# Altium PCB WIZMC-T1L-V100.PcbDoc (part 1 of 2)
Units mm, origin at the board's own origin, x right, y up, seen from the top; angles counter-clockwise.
Board outline 48.5 x 42.5 mm, 4 copper layers (Top Layer, GND, POWER, Bottom Layer), stack 0.603 mm thick; 133 components, 92 nets, 478 pads, 203 vias.
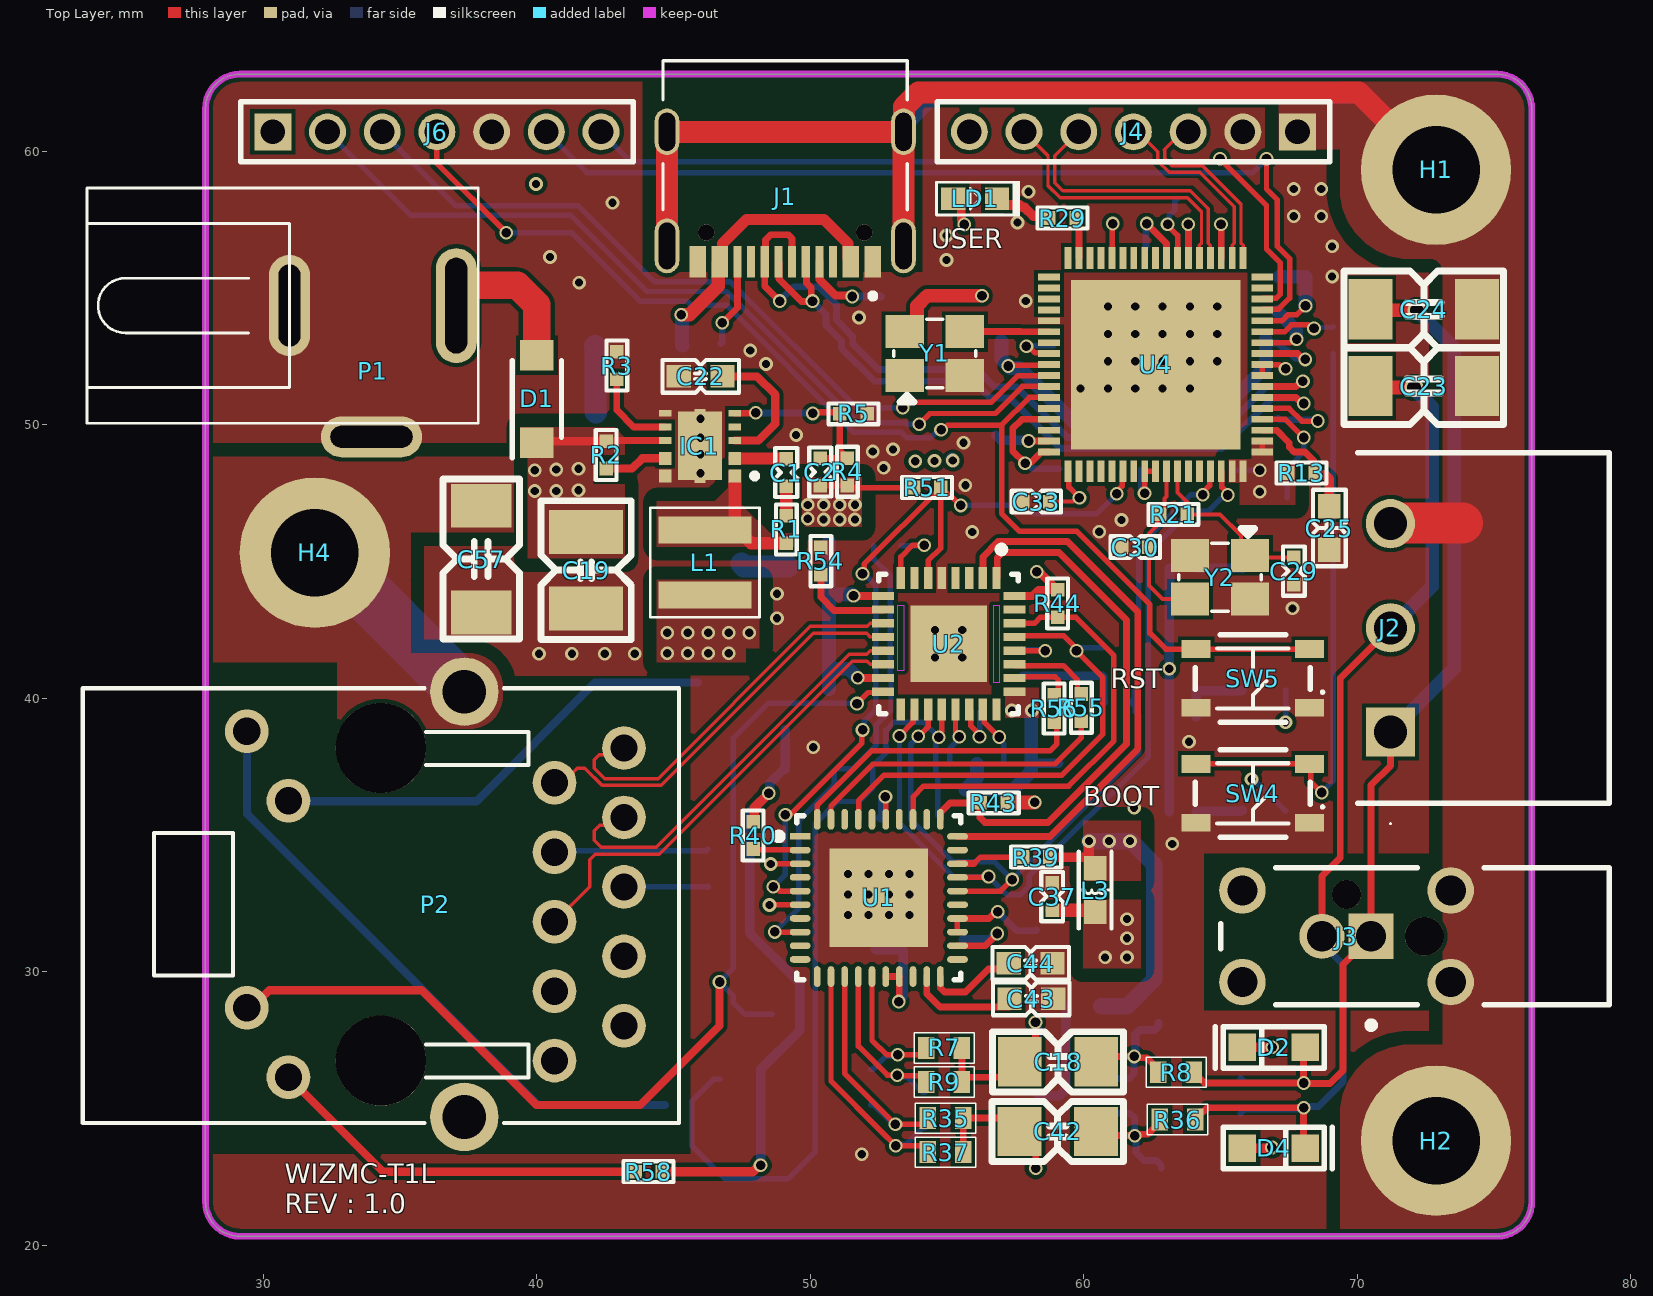
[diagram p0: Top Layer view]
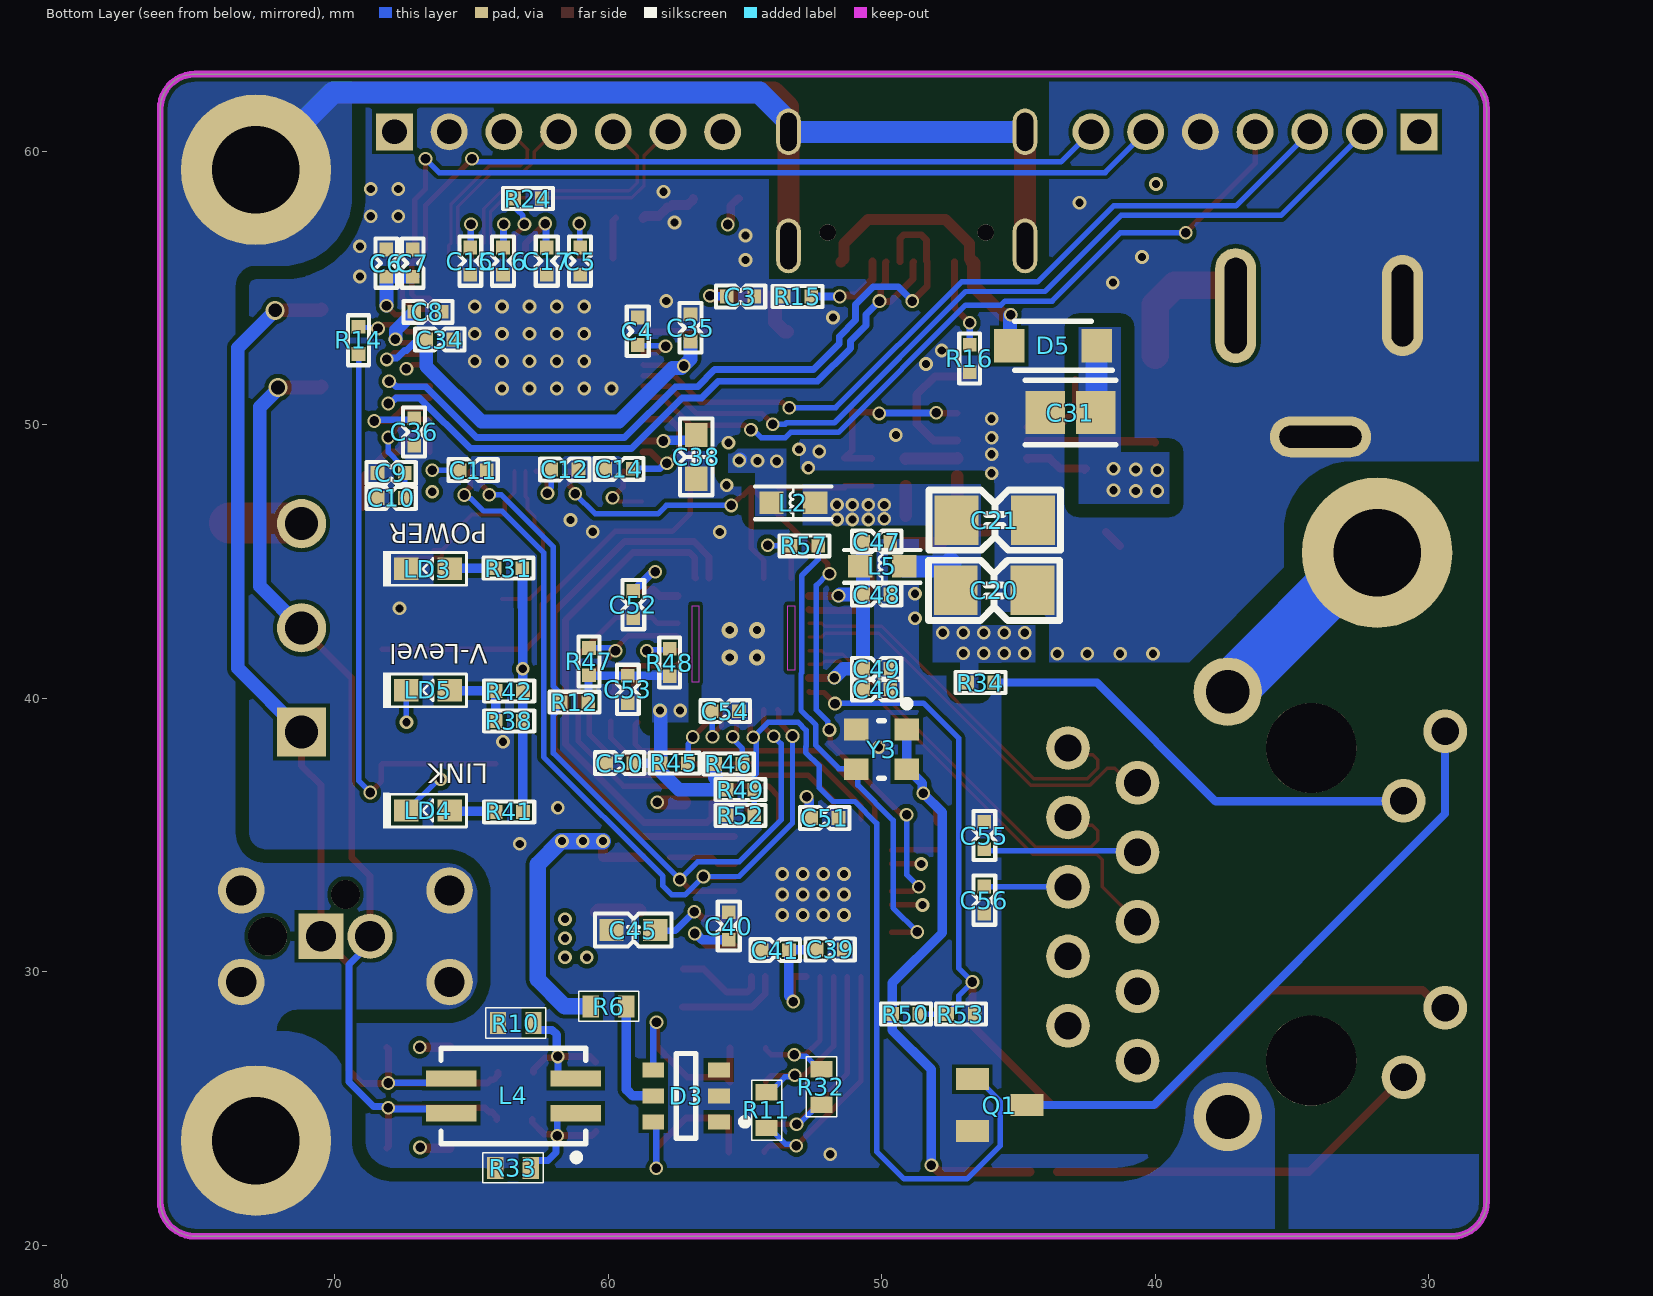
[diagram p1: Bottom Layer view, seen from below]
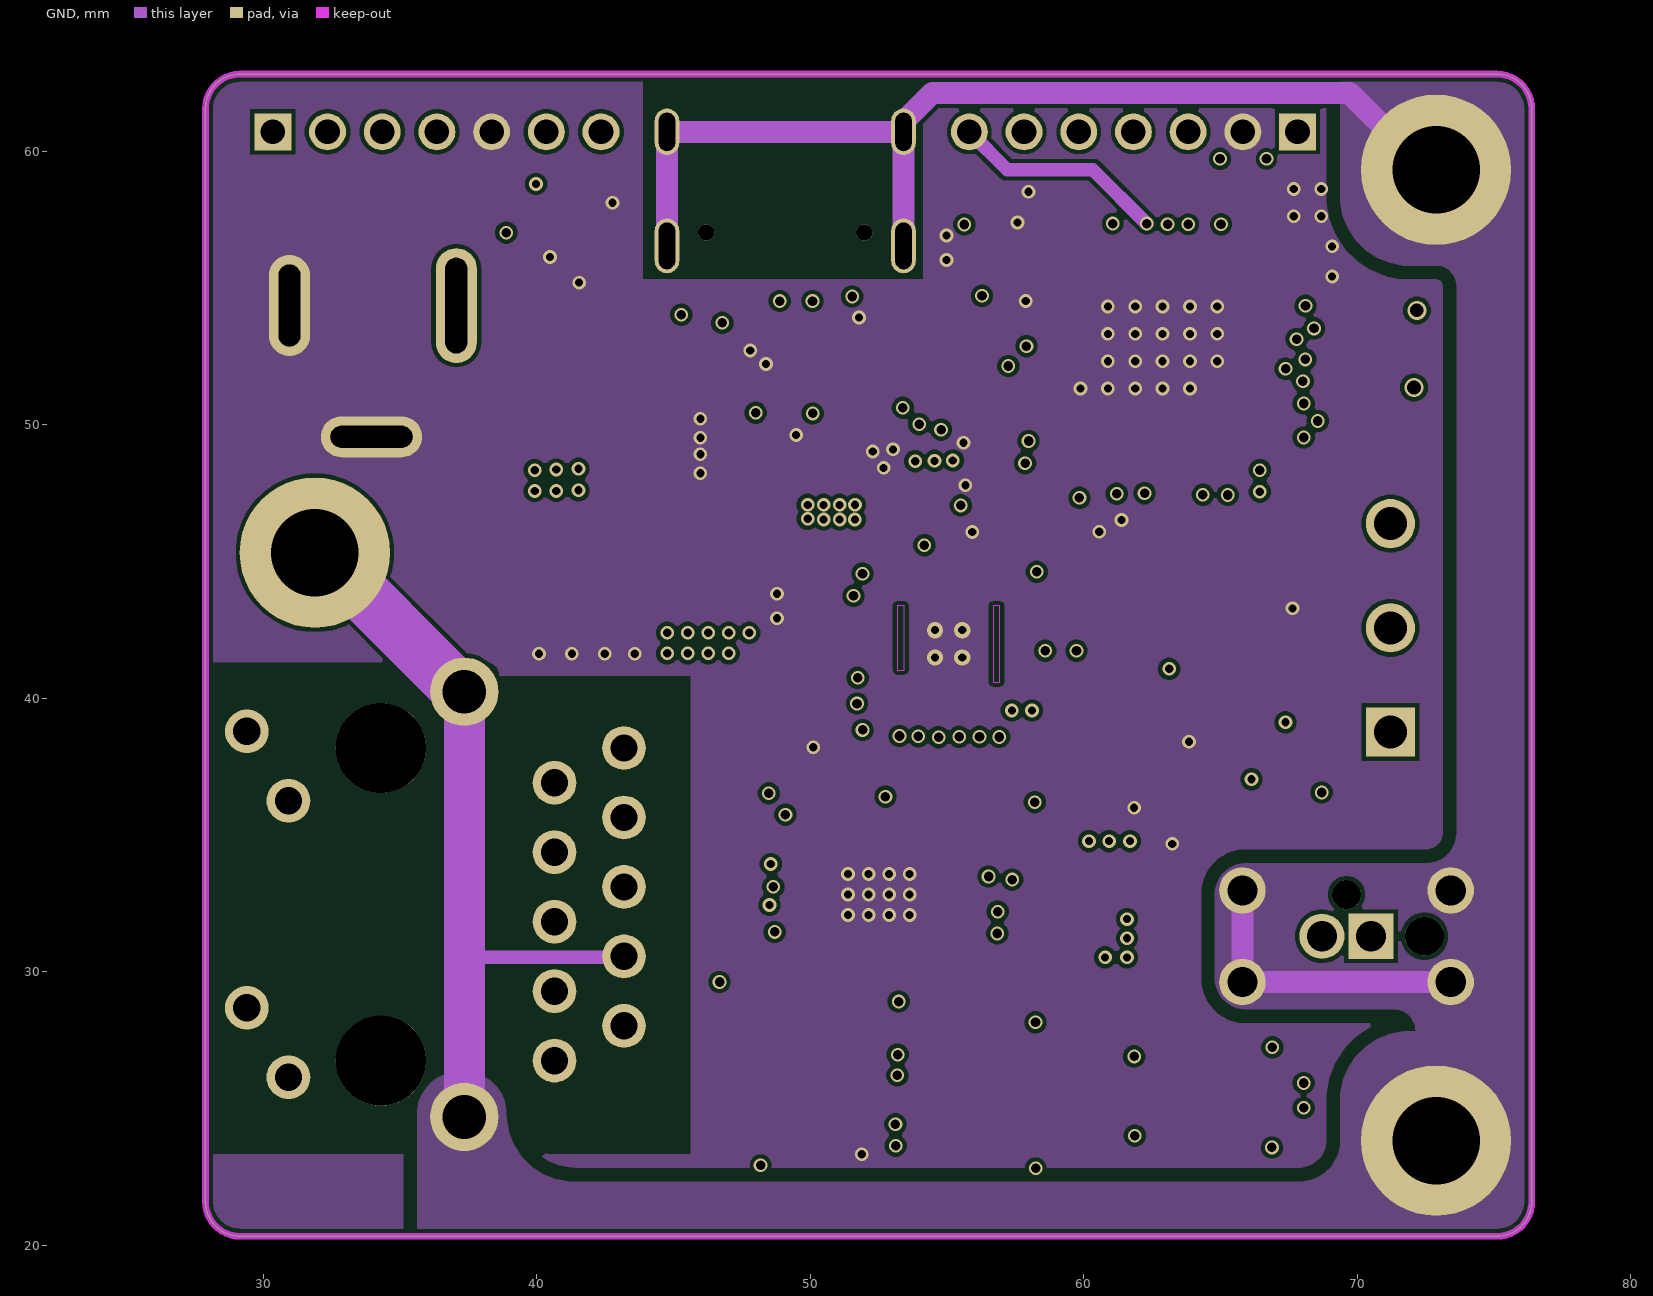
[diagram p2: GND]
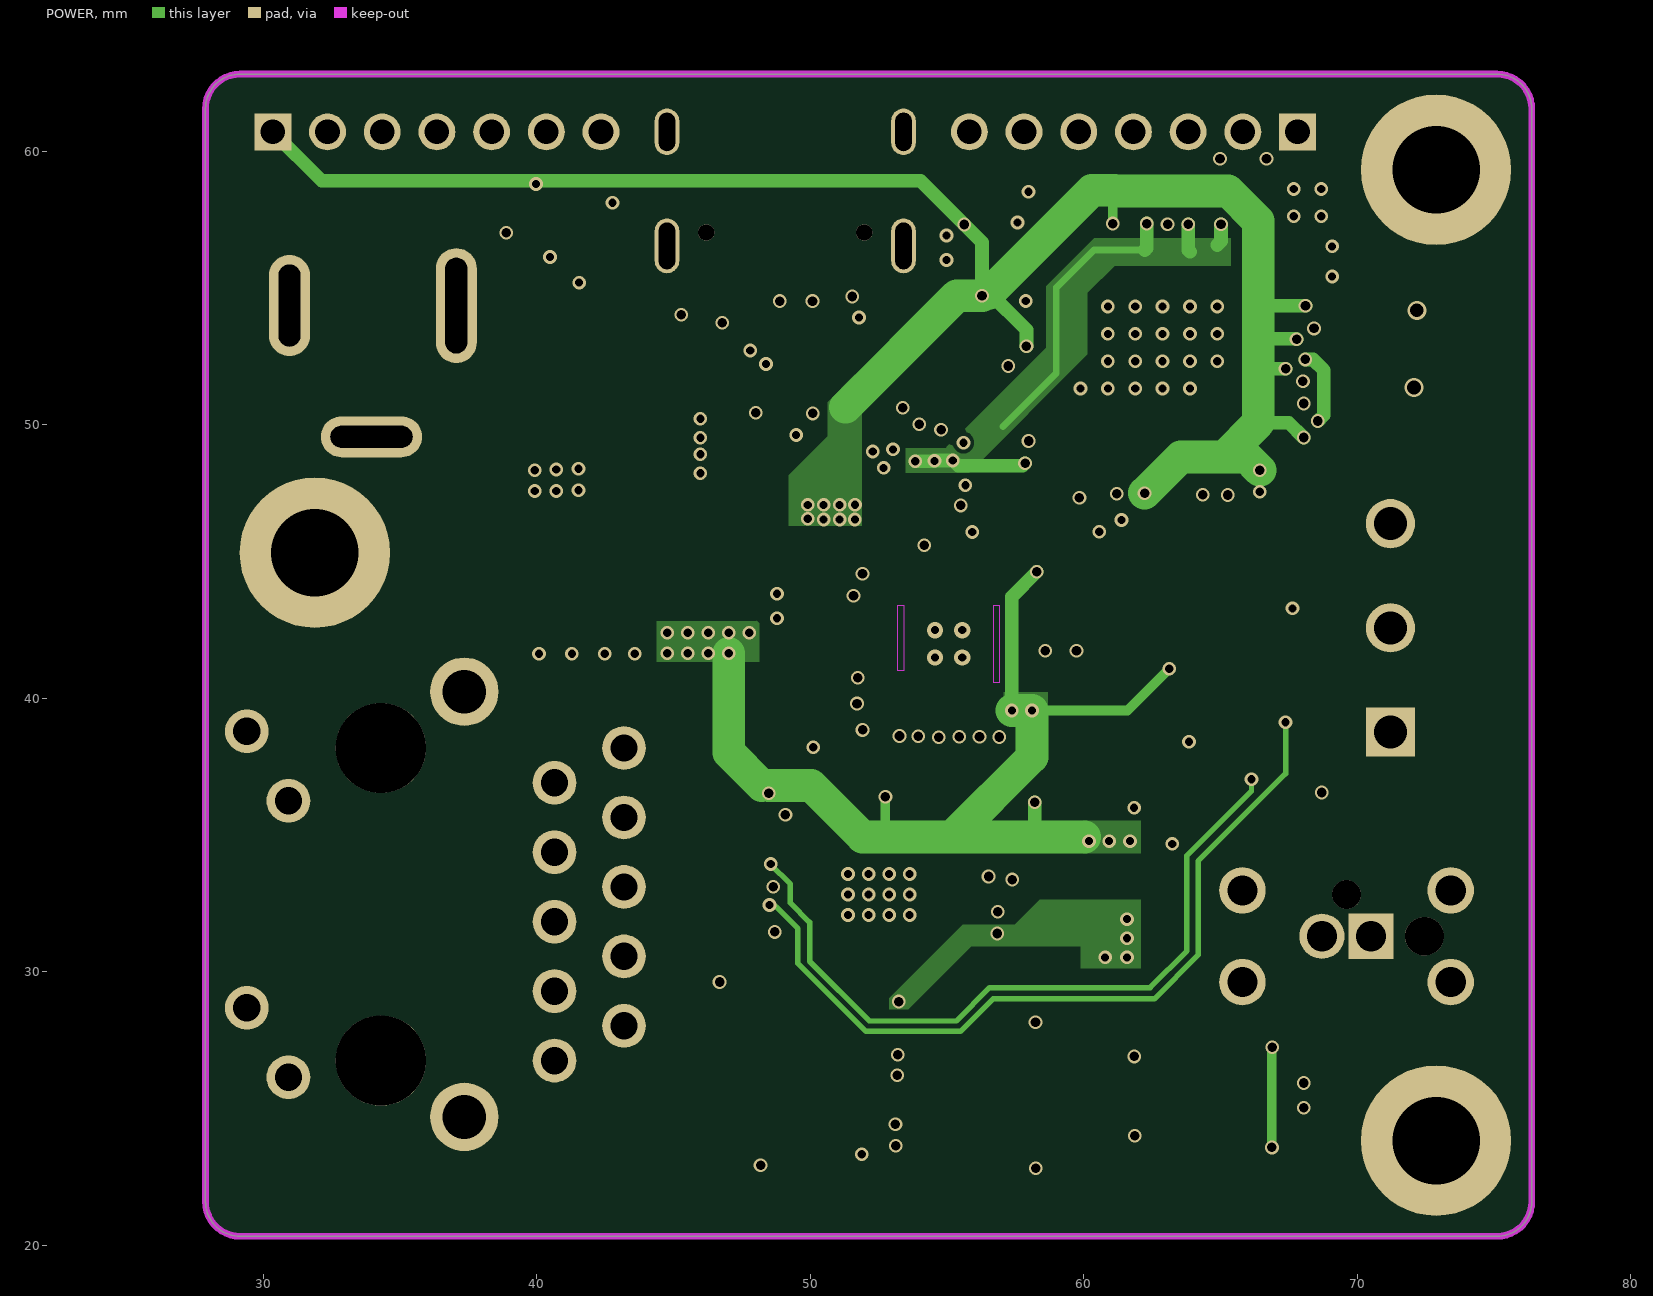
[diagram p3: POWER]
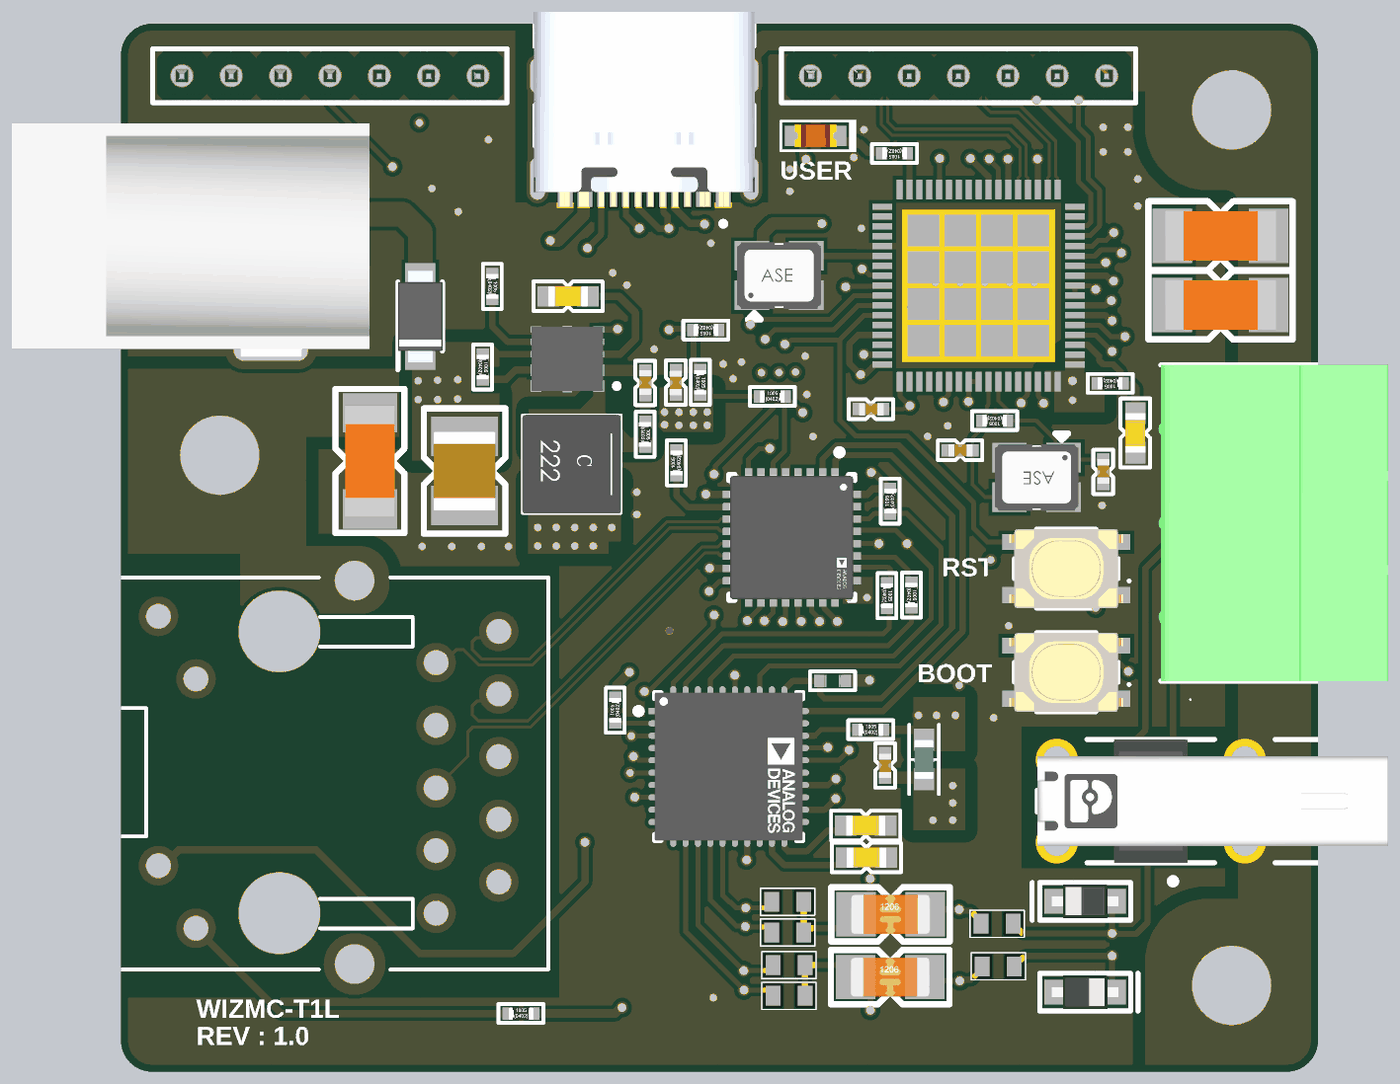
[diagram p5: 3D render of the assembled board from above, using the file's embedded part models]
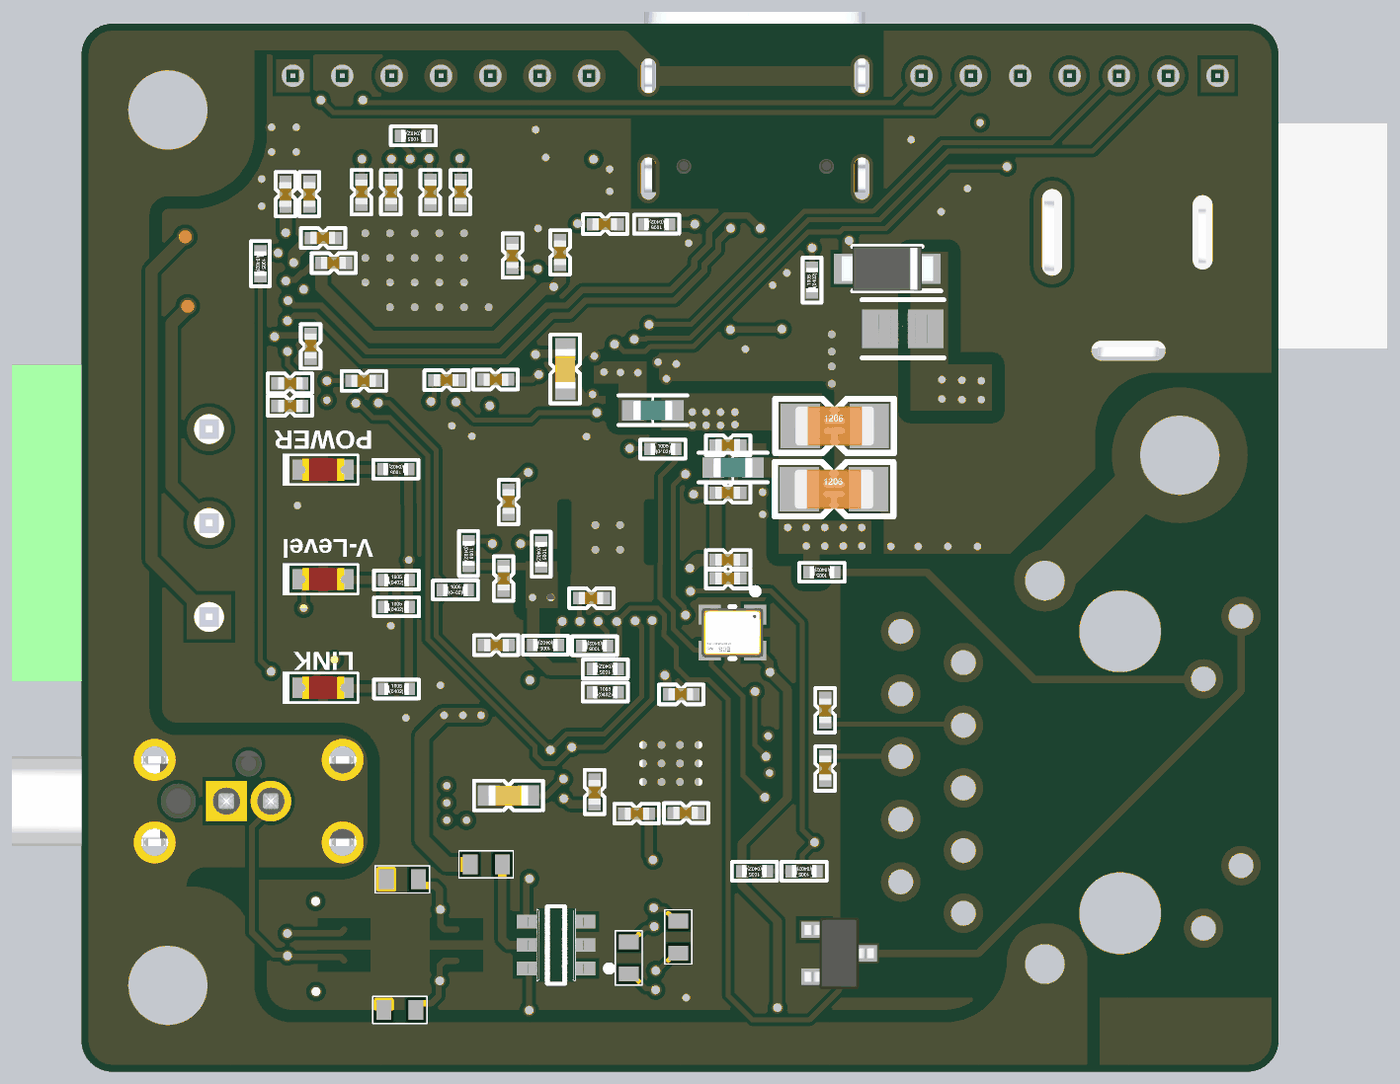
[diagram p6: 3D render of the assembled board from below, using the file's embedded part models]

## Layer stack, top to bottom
Top Solder: solder mask 0.0102, Solder Resist, Dk 3.5
Top Layer: signal copper 0.035
Dielectric 2: prepreg 0.0711, PP-006, Dk 4.1
GND: signal copper 0.0356
Dielectric 1: dielectric 0.32, FR-4, Dk 4.8
POWER: signal copper 0.0356
Dielectric 3: prepreg 0.0711, PP-006, Dk 4.1
Bottom Layer: signal copper 0.035
Bottom Solder: solder mask 0.0102, Solder Resist, Dk 3.5

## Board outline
27.877,21.59 27.877,61.55 cw(c29.147,61.55) 29.147,62.82 75.107,62.82 cw(c75.107,61.55) 76.377,61.55 76.377,21.59 cw(c75.107,21.59) 75.107,20.32 29.147,20.32 cw(c29.147,21.59)

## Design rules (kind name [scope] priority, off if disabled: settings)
Clearance [All] p1: gap=0.15 ignorepadtopadclearanceinfootprint=FALSE except(0.5: Poly-Poly)
DiffPairsRouting [All] p1: maxlimit=0.254 minlimit=0.1 mostfreqgap=0.254 toplayer_prefgap=0.125 toplayer_minwidth=0.1 toplayer_maxwidth=0.381 toplayer_prefwidth=0.125 midlayer1_mingap=0.254 midlayer1_minwidth=0.381 midlayer1_maxwidth=0.381 midlayer1_prefwidth=0.381 midlayer2_mingap=0.254 midlayer2_minwidth=0.381 midlayer2_maxwidth=0.381 midlayer2_prefwidth=0.381 bottomlayer_prefgap=0.125 bottomlayer_minwidth=0.1 bottomlayer_maxwidth=0.381 bottomlayer_prefwidth=0.125 maxuncoupledlength=12.7
PolygonConnect [All] p1: connectstyle=Direct reliefconductorwidth=0.254 reliefentries=4 polygonreliefangle="90 Angle" airgapwidth=0.254
RoutingVias [All] p1: holewidth=0.3 width=0.5 viastyle="Through Hole" minholewidth=0.1 minwidth=0.1 maxholewidth=1 maxwidth=1.27
SolderMaskExpansion [All] p1: expansion=0.102 istentingtop=TRUE
Width [All] p1: maxlimit=2 minlimit=0.1 preferedwidth=0.254 minimp=50.000000 maximp=50.000000 favimp=50.000000
29 further rules are at their usual default settings.

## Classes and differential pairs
component class WIZMD-W55RP20: C1 C2 C3 C4 C5 C6 C7 C8 C9 C10 C11 C12 C14 C15 C16 C17 C19 C20 C21 C22 C25 C29 C30 C31 C33 C34 C35 C36 C38 D1 D5 H1 H2 H4 IC1 J1 J4 J6 L1 L2 LD1 LD3 P1 R1 R2 R3 R4 R5 R12 R13 R14 R15 R16 R21 R24 R29 R31 SW4 SW5 U4 Y1 Y2
component class WIZMD-ADIN1200: C46 C47 C48 C49 C50 C51 C52 C53 C54 C55 C56 C57 L5 P2 Q1 R34 R45 R46 R47 R48 R49 R50 R51 R52 R53 R54 R55 R56 R57 R58 U2
component class WIZMD-ADIN1100: C18 C23 C24 C37 C39 C40 C41 C42 C43 C44 C45 D2 D3 D4 J2 J3 L3 L4 LD4 LD5 R6 R7 R8 R9 R10 R11 R32 R33 R35 R36 R37 R38 R39 R40 R41 R42 R43 R44 U1 Y3
differential pair MDI_1: +MDI_1_P -MDI_1_N
differential pair MDI_0: +MDI_0_P -MDI_0_N
differential pair USB: +USB_P -USB_N
differential pair T: +T_P -T_N
differential pair R: +R_P -R_N

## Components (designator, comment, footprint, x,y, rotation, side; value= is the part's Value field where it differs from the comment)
C1 "100nF" CAP-0402 49.116,48.251 r90 top
C2 "15pF" CAP-0402 50.359,48.268 r270 top
C3 "1uF" CAP-0402 55.156,54.686 r0 bottom
C4 "0.1uF" CAP-0402 58.916,53.416 r270 bottom
C5 "0.1uF" CAP-0402 61.024,55.982 r90 bottom
C6 "0.1uF" CAP-0402 68.11,55.905 r270 bottom
C7 "0.1uF" CAP-0402 67.145,55.905 r270 bottom
C8 "0.1uF" CAP-0402 66.586,54.127 r0 bottom
C9 "0.1uF" CAP-0402 67.933,48.235 r180 bottom
C10 "0.1uF" CAP-0402 67.933,47.32 r180 bottom
C11 "0.1uF" CAP-0402 64.935,48.336 r0 bottom
C12 "0.1uF" CAP-0402 61.583,48.362 r0 bottom
C14 "0.1uF" CAP-0402 59.601,48.387 r180 bottom
C15 "0.1uF" CAP-0402 65.037,55.982 r90 bottom
C16 "1uF" CAP-0402 63.843,55.982 r90 bottom
C17 "0.1uF" CAP-0402 62.243,55.982 r90 bottom
C18 "0.22uF / 100V" CAP-1206 59.055,26.7 r0 top
C19 "4.7uF / 100V" CAP-1210 41.796,44.679 r90 top
C20 "22uF/10V" CAP-1206 45.885,43.942 r180 bottom
C21 "22uF/10V" CAP-1206 45.86,46.507 r180 bottom
C22 "1uF" CAP-0603 45.987,51.765 r0 top
C23 "100pF/3kV" CAP-1808 72.428,51.41 r180 top
C24 "100pF/3kV" CAP-1808 72.428,54.218 r180 top
C25 "2.2uF" CAP-0603 68.977,46.22 r90 top
C29 "18pF" CAP-0402 67.675,44.645 r90 top
C30 "18pF" CAP-0402 61.877,45.52 r0 top
C31 "10uF" CAP-0805 43.091,50.444 r180 bottom
C33 "10nF" CAP-0402 58.263,47.187 r0 top
C34 "1uF" CAP-0402 66.155,53.111 r0 bottom
C35 "0.1uF" CAP-0402 56.985,53.543 r270 bottom
C36 "0.1uF" CAP-0402 67.094,49.733 r90 bottom
C37 "0.1uF" CAP-0402 58.839,32.741 r270 top
C38 "4.7uF" CAP-0603 56.777,48.82 r90 bottom
C39 "0.1uF" CAP-0402 51.88,30.81 r0 bottom
C40 "0.1uF" CAP-0402 55.588,31.666 r270 bottom
C41 "0.1uF" CAP-0402 53.886,30.785 r180 bottom
C42 "0.22uF / 100V" CAP-1206 59.043,24.155 r0 top
C43 "1uF/16V" CAP-0603 58.077,29.007 r0 top
C44 "1uF/16V" CAP-0603 58.052,30.302 r0 top
C45 "1uF/16V" CAP-0603 59.077,31.52 r180 bottom
C46 "0.1uF" CAP-0402 50.177,40.32 r0 bottom
C47 "0.1uF" CAP-0402 50.177,45.72 r0 bottom
C48 "0.1uF" CAP-0402 50.178,43.79 r0 bottom
C49 "0.1uF" CAP-0402 50.178,41.072 r0 bottom
C50 "0.1uF" CAP-0402 59.577,37.62 r180 bottom
C51 "0.1uF" CAP-0402 52.077,35.62 r0 bottom
C52 "0.1uF" CAP-0402 59.077,43.42 r90 bottom
C53 "0.1uF" CAP-0402 59.277,40.32 r90 bottom
C54 "0.1uF" CAP-0402 55.715,39.522 r0 bottom
C55 "0.1uF" CAP-0402 46.241,34.976 r270 bottom
C56 "0.1uF" CAP-0402 46.241,32.614 r90 bottom
C57 "1nF/2kV" CAP-1808 37.961,45.085 r90 top
D1 "SS1FN6-M3_I" SODFL3718X108N 39.998,50.943 r90 top
D2 "CDSOD323-T36SC" SOD-323(1-C,2-A) 66.942,27.229 r0 top
D3 "DT1042-04SO-7" FP-SOT26_SC74R-MFG 57.15,25.455 r0 bottom value=0.65pF
D4 "CDSOD323-T36SC" SOD-323(1-C,2-A) 66.942,23.546 r180 top
D5 "SS1FN6-M3_I" SODFL3718X108N 43.726,52.883 r0 bottom
H1 "PCB Hole" M3_HOLE 72.877,59.32 r180 top
H2 "PCB Hole" M3_HOLE 72.877,23.82 r180 top
H4 "PCB Hole" M3_HOLE 31.877,45.32 r180 top
IC1 "XC9702A75CDR-G" XC9135B18CDRG 45.962,49.225 r180 top
J1 "*" USB-C 49.079,60.706 r180 top
J2 "Pluggable Terminal Block" 1803280 71.209,38.76 r90 top locked
J3 "1163797" FP-1163797-MFG 72.104,31.293 r180 top
J4 "2.54mm 1x9 Pin Header DIP" Pin-Header(DIP)_7x1_2.0mm 67.811,60.706 r180 top
J6 "NC/Pin Header 7x1_2.0mm" Pin-Header(DIP)_7x1_2.0mm 30.342,60.706 r0 top
L1 "VLS4020CX-220M-H" XAL40XX 46.139,44.958 r270 top
L2 "HH-1M1608-121JT" IND-0603 53.226,47.142 r0 bottom
L3 "HH-1M1608-121JT" IND-0603 60.414,32.982 r270 top
L4 "744242471" WE-SLM_L6W3.3H3.3 1333.46,-1244.545 r0 bottom
L5 "HH-1M1608-121JT" IND-0603 49.977,44.82 r0 bottom
LD1 "Red" LED-0603-RED 56.02,58.268 r0 top
LD3 "BLUE" LED-0603-RED 66.586,44.729 r0 bottom
LD4 "Red" LED-0603-RED 66.585,35.89 r0 bottom
LD5 "Red" LED-0603-RED 66.585,40.284 r0 bottom
P1 "DC-JACK 2pi" "DC-JACK 2pi" 27.15,54.356 r270 top
P2 "TRJ4284BHNL" RB1-ZZ-0049 34.292,32.461 r270 top locked
Q1 "Q-2N7002" SOT23-3L 45.677,25.12 r270 bottom
R1 "10R" RES-0402 49.116,46.168 r270 top
R2 "1K" RES-0402 42.533,48.895 r270 top
R3 "1K" RES-0402 42.919,52.162 r270 top
R4 "680k/1%" RES-0402 51.35,48.276 r270 top
R5 "200k/1%" RES-0402 51.575,50.394 r180 top
R6 "10K" RES-0603 59.982,28.727 r180 bottom
R7 "49.9R" RES-0603 54.889,27.208 r0 top
R8 "10K" RES-0603 63.373,26.319 r180 top
R9 "4.99k" RES-0603 54.889,25.963 r0 top
R10 "100K" RES-0603 63.377,28.12 r0 bottom
R11 "10K" RES-0603 54.204,24.932 r90 bottom
R12 "4.7k" RES-0402 61.227,39.853 r180 bottom
R13 "200R" RES-0402 67.958,48.235 r180 top
R14 "1K" RES-0402 69.126,53.086 r270 bottom
R15 "5.1k" RES-0402 53.074,54.686 r0 bottom
R16 "5.1k" RES-0402 46.777,52.42 r90 bottom
R21 "1M" RES-0402 63.277,46.72 r180 top
R24 "12.4K 1%" RES-0402 62.929,58.268 r0 bottom
R29 "470R" RES-0402 59.22,57.556 r180 top
R31 "470R" RES-0402 63.64,44.755 r0 bottom
R32 "10K" RES-0603 52.197,25.785 r90 bottom
R33 "100K" RES-0603 63.477,22.82 r180 bottom
R34 "330R" RES-0402 46.377,40.57 r0 bottom
R35 "4.99k" RES-0603 54.94,24.642 r0 top
R36 "10K" RES-0603 63.424,24.592 r180 top
R37 "49.9R" RES-0603 54.94,23.398 r0 top
R38 "4.7k" RES-0402 63.615,39.167 r180 bottom
R39 "4.7k" RES-0402 58.255,34.188 r0 top
R40 "4.7k" RES-0402 47.904,34.98 r90 top
R41 "470R" RES-0402 63.615,35.839 r180 bottom
R42 "470R" RES-0402 63.615,40.259 r180 bottom
R43 "NC/4.7k" RES-0402 56.706,36.17 r0 top
R44 "4.7k" RES-0402 59.043,43.459 r90 top
R45 "10K" RES-0402 57.577,37.62 r0 bottom
R46 "10K" RES-0402 55.588,37.592 r0 bottom
R47 "4.7K" RES-0402 60.698,41.336 r270 bottom
R48 "4.7K" RES-0402 57.747,41.3 r270 bottom
R49 "10K" RES-0402 55.156,36.652 r0 bottom
R50 "10K" RES-0402 49.111,28.448 r0 bottom
R51 "100K" RES-0402 54.267,47.701 r0 top
R52 "56K" RES-0402 55.156,35.712 r180 bottom
R53 "NC/56K" RES-0402 47.097,28.448 r0 bottom
R54 "3K" RES-0402 50.381,45.009 r90 top
R55 "22R" RES-0402 59.906,39.649 r270 top
R56 "22R" RES-0402 58.916,39.624 r270 top
R57 "22R" RES-0402 52.82,45.568 r180 bottom
R58 "330R" RES-0402 44.082,22.682 r0 top
SW4 "1188(SMD)" 1188 66.177,36.52 r180 top
SW5 "1188(SMD)" 1188 66.177,40.72 r180 top
U1 "ADIN1100CCPZ-R7" FP-CP-40-29-IPC_C 52.502,32.694 r0 top
U2 "ADIN1200CCP32Z" FP-CP-32-31-MFG 55.055,41.986 r270 top
U4 "W55RP20" QFN68 62.624,52.197 r270 top
Y1 "12MHz" 3225_XTAL 54.547,52.603 r0 top
Y2 "25MHz" OSC-82J0626 64.977,44.42 r180 top
Y3 "ECS-2520MVLC-081.92-BN-TR" FP-ECS-2520MVLC-MFG 50,38.125 r0 bottom

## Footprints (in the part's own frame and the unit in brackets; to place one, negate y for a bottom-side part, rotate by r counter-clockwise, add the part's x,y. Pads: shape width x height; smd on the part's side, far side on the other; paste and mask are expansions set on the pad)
1188 [mm]
  rect 1.05x0.65 smd: 1(-2.075,1.075) 2(2.075,1.075) 3(-2.075,-1.075) 4(2.075,-1.075)
  silkscreen extent -2.6,-1.6 2.1,1.6, body extent -2.3,-1.6 2.3,1.6, height 2.53
3225_XTAL [mm]
  rect 1.4x1.2 smd: 1(-1.1,-0.8) 2(1.1,-0.8) 3(1.1,0.8) 4(-1.1,0.8)
  silkscreen extent -1.5,-1.78 1.5,1.25, body extent -1.7,-1.35 1.7,1.35, height 1.06
1803280 [mm]
  rect 1.8x1.8 hole 1.2: 1(0,0)
  round 1.8 hole 1.2: 2(3.81,0) 3(7.62,0)
  silkscreen extent -3.38,-8 10.22,1.2, body extent -2.6,-8 10.22,1.3, height 7.26
CAP-0402 [mm]
  rect 0.5x0.5 smd: 1(-0.5,0) 2(0.5,0)
  silkscreen extent -0.9,-0.4 0.9,0.4, body extent -0.48,-0.25 0.52,0.25, height 0.6
CAP-0603 [mm] "Ceramic CAP 0603(1608)"
  rect 0.89x0.82 smd: 1(-0.8,0) 2(0.8,0)
  silkscreen extent -1.4,-0.6 1.4,0.6, body extent -0.93,-0.41 0.93,0.41, height 0.81
CAP-0805 [mm]
  rect 1.455x1.556 smd paste+0 mask+0: 1(-0.926,0) 2(0.926,0)
  silkscreen extent -1.65,-1.18 1.65,1.18, body extent -1,-0.62 1,0.62, height 1.45
CAP-1206 [mm]
  rect 1.6x1.8 smd: 1(-1.4,0) 2(1.4,0)
  silkscreen extent -2.4,-1.1 2.4,1.1, body extent -1.6,-0.8 1.6,0.8, height 1
CAP-1210 [mm]
  rect 1.6x2.7 smd: 1(-1.4,0) 2(1.4,0)
  silkscreen extent -2.54,-1.65 2.54,1.65, body extent -1.6,-1.25 1.6,1.25, height 1.3
CAP-1808 [mm] "Ceramic CAP 1808(4520)"
  rect 1.6x2.2 smd: 1(-1.95,0) 2(1.95,0)
  silkscreen extent -2.92,-1.4 2.92,1.4, body extent -2.25,-1.02 2.25,1.01, height 2
"DC-JACK 2pi" [mm] "DC-JACK 2pi"
  oval 4.2x1.5 hole 0.8 slot 3.5 at 0 deg: 1(0,9.9)
  oval 1.5x3.7 hole 0.8 slot 3 at 90 deg: 2(4.8,6.8)
  oval 3.7x1.5 hole 0.8 slot 3 at 0 deg: 3(0,3.8)
  silkscreen extent -4.3,-3.6 4.3,10.7, body extent -4.42,-3.69 5.05,10.79, height 11.18
FP-1163797-MFG [mm]
  rect 1.65x1.65 hole 1.1 paste-1000 mask+0: 1(1.6,0)
  round 1.65 hole 1.1 paste-1000 mask+0: 2(3.4,0)
  round 1.7 hole 1.1 paste-1000 mask+0: 3(-1.31,1.675) 4(6.31,1.675) 5(-1.31,-1.675) 6(6.31,-1.675)
  round 1.42 hole 1.42 unplated paste-1000 mask+0: ""(-0.35,0)
  round 1.05 hole 1.05 unplated paste-1000 mask+0: ""(2.5,-1.525)
  silkscreen extent -7.1,-2.5 7.1,3.37, body extent -7.2,-2.63 7.26,2.63, height 0.25
FP-CP-32-31-MFG [mm]
  rect 0.805x0.3 smd paste+0 mask+0: 1(-2.402,1.75) 2(-2.402,1.25) 3(-2.402,0.75) 4(-2.402,0.25) 5(-2.402,-0.25) 6(-2.402,-0.75) 7(-2.402,-1.25) 8(-2.402,-1.75) 17(2.402,-1.75) 18(2.402,-1.25) 19(2.402,-0.75) 20(2.402,-0.25) 21(2.402,0.25) 22(2.402,0.75) 23(2.402,1.25) 24(2.402,1.75)
  rect 0.3x0.805 smd paste+0 mask+0: 9(-1.75,-2.402) 10(-1.25,-2.402) 11(-0.75,-2.402) 12(-0.25,-2.402) 13(0.25,-2.402) 14(0.75,-2.402) 15(1.25,-2.402) 16(1.75,-2.402) 25(1.75,2.402) 26(1.25,2.402) 27(0.75,2.402) 28(0.25,2.402) 29(-0.25,2.402) 30(-0.75,2.402) 31(-1.25,2.402) 32(-1.75,2.402)
  rect 2.8x2.8 smd paste+0 mask+0: 33(0,0)
  Keep-Out Layer region: -1.4,-1.875 0.97,-1.875 0.97,-1.625 -1.4,-1.625
  Keep-Out Layer region: -1.4,1.625 1.4,1.625 1.4,1.875 -1.4,1.875
  silkscreen extent -3.57,-2.55 2.55,2.55, body extent -2.91,-2.91 2.91,2.91, height 0.25
FP-CP-40-29-IPC_C [mm]
  rect 0.761x0.242 smd paste+0 mask+0: 1(-2.876,2.25)
  rrect100% 0.761x0.242 smd paste+0 mask+0: 2(-2.876,1.75) 3(-2.876,1.25) 4(-2.876,0.75) 5(-2.876,0.25) 6(-2.876,-0.25) 7(-2.876,-0.75) 8(-2.876,-1.25) 9(-2.876,-1.75) 10(-2.876,-2.25) 21(2.876,-2.25) 22(2.876,-1.75) 23(2.876,-1.25) 24(2.876,-0.75) 25(2.876,-0.25) 26(2.876,0.25) 27(2.876,0.75) 28(2.876,1.25) 29(2.876,1.75) 30(2.876,2.25)
  rrect100% 0.242x0.761 smd paste+0 mask+0: 11(-2.25,-2.876) 12(-1.75,-2.876) 13(-1.25,-2.876) 14(-0.75,-2.876) 15(-0.25,-2.876) 16(0.25,-2.876) 17(0.75,-2.876) 18(1.25,-2.876) 19(1.75,-2.876) 20(2.25,-2.876) 31(2.25,2.876) 32(1.75,2.876) 33(1.25,2.876) 34(0.75,2.876) 35(0.25,2.876) 36(-0.25,2.876) 37(-0.75,2.876) 38(-1.25,2.876) 39(-1.75,2.876) 40(-2.25,2.876)
  rect 3.6x3.6 smd paste-1000 mask+0: 41(0,0)
  silkscreen extent -3.78,-3 3,3, body extent -3.36,-3.36 3.36,3.36, height 0.25
FP-ECS-2520MVLC-MFG [mm]
  rect 0.9x0.8 smd paste+0 mask+0: 1(-0.925,-0.725) 2(0.925,-0.725) 3(0.925,0.725) 4(-0.925,0.725)
  silkscreen extent -1.05,-1.8 0.1,1.05, body extent -1.25,-1 1.25,1, height 0.9
FP-SOT26_SC74R-MFG [mm]
  rect 0.8x0.55 smd paste+0 mask+0: 1(-1.2,0.95) 2(-1.2,0) 3(-1.2,-0.95) 4(1.2,-0.95) 5(1.2,0) 6(1.2,0.95)
  silkscreen extent -2.27,-1.55 0.35,1.55, body extent -1.4,-1.5 1.4,1.5, height 1.15
IND-0603 [mm] "Inductor 0603(1608)"
  rect 0.89x0.82 smd: 1(-0.8,0) 2(0.8,0)
  silkscreen extent -1.4,-0.6 1.4,0.6, body extent -0.8,-0.4 0.8,0.4, height 0.95
LED-0603-RED [mm] "LED-0603-RED"
  rect 0.89x0.82 smd: 1(-0.8,0) 2(0.8,0)
  silkscreen extent -1.41,-0.65 1.65,0.65, body extent -0.85,-0.45 0.85,0.45, height 0.9
M3_HOLE [mm]
  round 5.5 hole 3.2: 1(0,0)
OSC-82J0626 [mm]
  rect 1.4x1.2 smd: 1(-1.1,-0.8) 2(1.1,-0.8) 3(1.1,0.8) 4(-1.1,0.8)
  silkscreen extent -1.5,-1.78 1.5,1.25, body extent -1.7,-1.35 1.7,1.35, height 1.06
Pin-Header(DIP)_7x1_2.0mm [mm]
  rect 1.35x1.35 hole 0.9: 1(0,0)
  round 1.35 hole 0.9: 2(2,0) 3(4,0) 4(6,0) 5(8,0) 6(10,0) 7(12,0)
  silkscreen extent -1.17,-1.1 13.18,1.1, body extent -1,-1 13,1, height 5
QFN68 [mm]
  rect 0.8x0.25 smd mask+0: 1(-3.9,3.2) 2(-3.9,2.8) 3(-3.9,2.4) 4(-3.9,2) 5(-3.9,1.6) 6(-3.9,1.2) 7(-3.9,0.8) 8(-3.9,0.4) 9(-3.9,0) 10(-3.9,-0.4) 11(-3.9,-0.8) 12(-3.9,-1.2) 13(-3.9,-1.6) 14(-3.9,-2) 15(-3.9,-2.4) 16(-3.9,-2.8) 17(-3.9,-3.2) 35(3.9,-3.2) 36(3.9,-2.8) 37(3.9,-2.4) 38(3.9,-2) 39(3.9,-1.6) 40(3.9,-1.2) 41(3.9,-0.8) 42(3.9,-0.4) 43(3.9,0) 44(3.9,0.4) 45(3.9,0.8) 46(3.9,1.2) 47(3.9,1.6) 48(3.9,2) 49(3.9,2.4) 50(3.9,2.8) 51(3.9,3.2)
  rect 0.25x0.8 smd mask+0: 18(-3.2,-3.9) 19(-2.8,-3.9) 20(-2.4,-3.9) 21(-2,-3.9) 22(-1.6,-3.9) 23(-1.2,-3.9) 24(-0.8,-3.9) 25(-0.4,-3.9) 26(0,-3.9) 27(0.4,-3.9) 28(0.8,-3.9) 29(1.2,-3.9) 30(1.6,-3.9) 31(2,-3.9) 32(2.4,-3.9) 33(2.8,-3.9) 34(3.2,-3.9) 52(3.2,3.9) 53(2.8,3.9) 54(2.4,3.9) 55(2,3.9) 56(1.6,3.9) 57(1.2,3.9) 58(0.8,3.9) 59(0.4,3.9) 60(0,3.9) 61(-0.4,3.9) 62(-0.8,3.9) 63(-1.2,3.9) 64(-1.6,3.9) 65(-2,3.9) 66(-2.4,3.9) 67(-2.8,3.9) 68(-3.2,3.9)
  rect 6.2x6.2 smd paste-4 mask+0: 69(0,0)
  body extent -4,-4 4,4, height 0.9
RB1-ZZ-0049 [mm]
  round 3.3 hole 3.3: 0(-5.715,0) 0(5.715,0)
  round 1.6 hole 1: L1(6.325,-3.38) L2(3.785,-4.9) L3(-3.785,-3.38) L4(-6.325,-4.9) R1(-5.715,8.89) R2(-4.445,6.35) R3(-3.175,8.89) R4(-1.905,6.35) R5(-0.635,8.89) R6(0.635,6.35) R7(1.905,8.89) R8(3.175,6.35) R9(4.445,8.89) R10(5.715,6.35)
  round 2.5 hole 1.6: S1(-7.775,3.05) S2(7.775,3.05)
  Top Layer pour cut-out: -8.8,-7.6 8.8,-7.6 8.8,-4.6 -8.8,-4.6
  Top Layer pour cut-out: -2.6,-8.3 -2.6,-5.4 2.6,-5.4 2.6,-8.3
  Top Layer pour cut-out: 5.13,1.65 5.13,5.4 6.33,5.4 6.33,1.65
  Top Layer pour cut-out: -6.3,1.65 -6.3,5.4 -5.1,5.4 -5.1,1.65
  silkscreen extent -7.9,-10.9 8,10.9, body extent -7.9,-10.9 8,10.9, height 13.35
RES-0402 [mm]
  rect 0.5x0.5 smd: 1(-0.5,0) 2(0.5,0)
  silkscreen extent -0.91,-0.38 0.91,0.38, body extent -0.5,-0.25 0.5,0.25, height 0.35
RES-0603 [mm] "Chip Resistor, 2-Leads, Body 1.60x0.80mm, IPC High Density"
  rect 0.6x0.8 smd paste+0 mask+0.102: 1(-0.65,0) 2(0.65,0)
  silkscreen extent -1.1,-0.55 1.1,0.55, body extent -0.85,-0.45 0.85,0.45, height 0.55
SOD-323(1-C,2-A) [mm]
  rect 1x1 smd: 1(-1.15,0) 2(1.15,0)
  silkscreen extent -2.15,-0.76 1.84,0.76, body extent -1.35,-0.67 1.35,0.68, height 0.79
SODFL3718X108N [mm]
  rect 1.12x1.22 smd: 1(-1.6,0) 2(1.6,0)
  silkscreen extent -2.16,-0.9 1.4,0.9, body extent -1.85,-0.9 1.85,0.9, height 1.08
SOT23-3L [mm]
  rect 0.8x1.2 smd paste-0.07: 1(-0.95,-1) 2(0.95,-1) 3(0,1)
  body extent -1.45,-1.4 1.45,1.4, height 1.28
USB-C [mm]
  rect 0.6x1.14 smd mask+0.05: A1_B12(-3.2,4.75) A4_B9(-2.4,4.75) B1_A12(3.2,4.75) B4_A9(2.4,4.75)
  rect 0.3x1.14 smd mask+0.05: A5(-1.25,4.75) A6(-0.25,4.75) A7(0.25,4.75) A8(1.25,4.75) B5(1.75,4.75) B6(0.75,4.75) B7(-0.75,4.75) B8(-1.75,4.75)
  oval 0.9x2 hole 0.6 slot 1.7 at 90 deg: S1(-4.325,4.17) S2(4.325,4.17)
  oval 0.9x1.7 hole 0.6 slot 1.4 at 90 deg: S3(-4.325,0) S4(4.325,0)
  round 0.6 hole 0.6 unplated: ""(-2.89,3.68) ""(2.89,3.68)
  silkscreen extent -4.47,-2.6 4.47,6.1, body extent -4.47,-2.6 4.47,5.31, height 3.31
WE-SLM_L6W3.3H3.3 [mm] "SMD Inductor, 4-Leads, Body 5x3.3mm"
  rect 1.85x0.6 smd: 1(-1272.275,-1269.365) 2(-1272.275,-1270.635) 3(-1267.725,-1270.635) 4(-1267.725,-1269.365)
  silkscreen extent -1272.65,-1271.75 -1267.35,-1267.63, body extent -1273,-1271.65 -1267,-1268.35, height 3.25
XAL40XX [mm]
  rect 0.98x3.4 smd: 1(-1.185,0) 2(1.185,0)
  silkscreen extent -2,-2 2,2, body extent -2,-2 2,2, height 2.1
XC9135B18CDRG [mm]
  rect 0.45x0.475 smd: 1(-1.275,1.106) 2(-1.275,0.456) 9(1.275,0.456) 10(1.275,1.106)
  rect 0.45x0.25 smd: 3(-1.275,-0.194) 4(-1.275,-0.694) 5(-1.275,-1.194) 6(1.275,-1.194) 7(1.275,-0.694) 8(1.275,-0.194)
  rect 1.6x2.5 smd: 11(0,0)
  rect 0.4x0.1 smd: A11(0,1.3) B11(0,-1.3)
  silkscreen extent -2.1,1 -1.9,1.2, body extent -1.45,-1.3 1.45,1.3, height 0.7

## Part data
C1 C2 C25 C29 C30 C33: library part CAP-0402, "MLCC-0402(1005)"
C3 C4 C5 C6 C7 C8 C9 C10 C11 C12 C14 C15 C16 C17 C34 C35 C36 C37 C39 C40 C41 C46 C47 C48 C49 C50 C51 C52 C53 C54 C55 C56: library part CAP-0402, "Ceramic CAP 0402(1005)"
C18 C20 C21 C42: library part CAP-1206, "MLCC-1206(3216)", Capacitance=1nF, Case Code (Imperial)=1206, Case Code (Metric)=3216, Dielectric=X7R, Dielectric Material=Ceramic, Manufacturer=KEMET, Manufacturer Part Number=C1206X102KGRACTU, Max Operating Temperature=125°C, Min Operating Temperature=-55°C, Package Quantity=1, Tolerance=10%, Voltage Rating=2kV
C19: library part CAP-1210, "MLCC-1210(3225)"
C22 C38 C43 C44 C45: library part CAP-0603, "MLCC-0603(1608)"
C23 C24: library part CAP-1808, "Ceramic CAP 1808(4520)"
C31: library part CAP-0805, "MLCC-0805(2012)"
C57: library part CAP-1808, "MLCC-1808(4520)"
D1 D5: "Schottky Diode", Arrow Part Number=SS1FN6-M3/I, Manufacturer_Name=Vishay, Mouser Part Number=78-SS1FN6-M3/I
D2 D4: "DIODE-TVS (SMB)", Manufacturer="Vishay Semiconductor", Manufacturer Part Number=SMAJ58CA-E3/61, Operating Junction and Storage Temperature Range="-55 to 150 degC"
D3: library part CMP-12828-000009-1, "TVS DIODE 5V 9V SOT26", Breakdown Voltage=6.2V, Capacitance=0.65pF, Clamping Voltage=6.3V, Manufacturer="Diodes Inc.", Package="SOT26 (SC74R)", Peak Pulse Current=6A, Peak Pulse Power=55W, Reverse Standoff Voltage=5V, Temperature="-55°C to +85°C", Temperature Range High=+85°C, Temperature Range Low=-55°C
H1 H2 H4: "PCB Supporter Hole"
IC1: "Integrated Circuit", Manufacturer_Name=Torex, Mouser Part Number=865-XC9702A75CDR-G
J1: library part TYPE-C-31-M-12, "USB Connectors 24 Receptacle 1 8.94*7.3mm RoHS", Package=Package
J2: "3Pos_3.81mm_Pluggable_Terminal_Blocks", Arrow Part Number=1803280, Manufacturer_Name="Phoenix Contact", Mouser Part Number=651-1803280
J3: library part CMP-09401-000002-1, "SPE PCB CONNECTOR, TYPE: IEC 631"
J4: library part "2.54mm 1x7 Pin Header"
J6: library part "Pin Header 7x1_2.0mm", "Connector", Manufacturer_Name=Harwin, Manufacturer_Part_Number=M22-2010705, Mouser Part Number=855-M22-2010705
L1: library part XAL4040-822MEC, "Inductor", Manufacturer_Name=COILCRAFT, Mouser Part Number=994-XAL4040-822MEC
L2 L3 L5: library part IND-0603, "Inductor 0603(1608)"
L4: library part CMP-03913-19122241-1, "744242471 Common Mode Chokes Dual 470uH 2.2kOhm 100kHz 400mA 350mOhm DCR SMD T/R", Ambient Temperature Range High=85°C, Ambient Temperature Range Low=-40°C, Case/Package=SMD/SMT, Current=400mA, DC Resistance (DCR)=350mΩ, Inductance=470µH, Max Operating Temperature=125°C, Test Frequency=100kHz, Tolerance=50%, Voltage Rating=80V
LD1 LD3 LD4 LD5: library part LED-0603, "LED-0603"
P2: library part RB1-ZZ-0049, "PoE RJ45"
Q1: "N-Channel 60-V (D-S) MOSFET"
R1 R2 R3 R4 R5 R12 R13 R14 R21 R24 R34 R58: library part RES-0402, "Chip Resistor 0402(1005)"
R6 R7 R8 R9 R10 R11 R32 R33 R35 R36 R37: library part RES-0603, "RES-0603"
R15 R16 R29 R31 R38 R39 R40 R41 R42 R43 R44 R45 R46 R47 R48 R49 R50 R51 R52 R53 R54 R55 R56 R57: library part RES-0402, "RES-0402"
SW4 SW5: "SMD TACT SWITCH"
U1: library part CMP-09095-000007-1, "10BASE-T1L PHY WITH 4 MDI"
U2: library part CMP-09095-000001-1, "INDUSTRIAL ETHERNET GIGABIT PHY", Ambient Temperature Range High=+105°C, Ambient Temperature Range Low=-40°C, Manufacturer="Analog Devices", Max Junction Temp=+125°C, Max Supply Voltage=3.46V, Min Supply Voltage=1.71V, Nominal Supply Current=20-31mA, Package=CP-32-31, Temperature="-40°C to +105°C"
U4: "WIZnet Hardwired TCP/IP Chip"
Y1: library part OSC-3225, "OSC 25MHz,3.2x2.5 SMD"
Y2: library part OSC-82J0626-25MHz, "X-tal 25MHz,3.2x2.5 SMD, CL=18pF"
Y3: library part CMP-40224-000048-1, "XTAL OSC XO 8.192MHZ CMOS SMD"

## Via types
v1: diameter 0.5, hole 0.3, Top Layer to Bottom Layer, tented both sides, 116 vias
v2: diameter 0.5, hole 0.35, Top Layer to Bottom Layer, tented both sides, 81 vias
v3: diameter 0.6, hole 0.3, Top Layer to Bottom Layer, tented both sides, 4 vias
v4: diameter 0.7, hole 0.5, Top Layer to Bottom Layer, tented both sides, 2 vias

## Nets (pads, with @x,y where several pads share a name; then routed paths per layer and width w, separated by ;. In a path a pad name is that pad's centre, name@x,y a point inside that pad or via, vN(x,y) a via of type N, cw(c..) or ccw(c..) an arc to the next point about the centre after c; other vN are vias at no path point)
1V1: C34.2 C35.2 C36.2 U4.26 U4.56 U4.61 | length 24.6
  Top Layer w0.2: v2(57.239,52.146) 57.265,52.172 58.699,52.172 U4.26@58.724,52.197 ; U4.56@66.524,50.597 67.505,50.597 67.969,50.133 v2(68.557,50.133)
  Top Layer w0.25: U4.61@66.524,52.597 67.817,52.597 68.029,52.385 v2(68.096,52.385)
  POWER w0.5: v2(68.096,52.385) 68.379,52.385 68.771,51.994 68.771,50.346 v2(68.557,50.133)
  Bottom Layer w0.25: C35.2@56.915,52.973 C35.2@56.985,53.043 ; C34.2@66.655,53.111 66.78,52.986 67.092,52.986 67.365,52.714 67.447,52.714 67.728,52.433 68.049,52.433 v2(68.096,52.385) ; C36.2@67.094,50.233 67.147,50.181 68.509,50.181 v2(68.557,50.133) v2@68.535,50.111
  Bottom Layer w0.5: C35.2@56.985,53.043 56.985,52.4 v2(57.239,52.146) 57.315,52.07 57.646,52.07 59.601,50.114 64.631,50.114 66.655,52.138 C34.2@66.655,53.111
2P4_EN: R43.1 U1.31 U2.1 | length 20.1
  Top Layer w0.25: U1.31@54.752,35.57 54.752,35.822 55.1,36.17 R43.1@56.206,36.17 56.206,35.628 56.376,35.458 58.687,35.458 61.557,38.329 61.557,42.85 59.084,45.323 57.027,45.323 56.83,45.126 56.83,44.414 U2.1@56.805,44.389
3V3: C2.2 C3.2 C4.2 C5.2 C6.2 C7.2 C8.2 C9.2 C10.2 C11.2 C12.2 C20.1 C21.1 C50.2 C51.2 C52.2 C53.2 J6.1 L1.2 L2.1 L3.1 L5.1 LD1.1 R4.2 R6.1 R12.2 R13.2 R31.1 R34.2 R38.2 R39.2 R40.2 R41.2 R42.2 R43.2 R44.2 R45.2 R46.2 R47.2 R48.2 R49.2 R50.2 R51.1 R58.2 U1.35 U2.25 U2.32 U4.13 U4.25 U4.42 U4.43 U4.50 U4.51 U4.52 U4.53 U4.55 U4.59 U4.60 U4.62 U4.64 Y1.4 Y3.1 Y3.4 | length 200.7
  Top Layer w0.2: C2.2@50.359,47.768 50.363,47.772 51.346,47.772 51.346,47.701 R51.1@53.767,47.701 ; v2(52.743,36.398) 52.748,36.394 52.748,35.574 U1.35@52.752,35.57 ; R43.2@57.206,36.17 R43.2@57.218,36.182 ; v2(57.9,52.872) 57.97,52.872 58.22,52.622 58.699,52.622 U4.25@58.724,52.597 ; U4.13@61.024,56.097 61.037,56.11 61.037,57.341 v2(61.049,57.353) ; v2(62.218,47.498) 62.221,47.501 62.221,48.294 U4.42@62.224,48.297 U4.43@62.624,48.297 ; U4.52@66.524,48.997 U4.53@66.524,49.397 ; U4.55@66.524,50.197 67.367,50.197 v2(68.034,49.53) ; U4.59@66.524,51.797 U4.60@66.524,52.197 67.14,52.197 ; U4.62@66.524,52.997 67.538,52.997 ; U4.64@66.524,53.797 67.242,53.797 67.473,54.027 67.787,54.027 v2(68.104,54.345)
  Top Layer w0.3: LD1.1@55.22,58.268 55.255,58.268 55.515,58.008 55.515,57.486 55.627,57.374 v2(55.627,57.32) ; U2.32@57.457,43.736 58.119,43.736 58.343,43.959 R44.2@59.043,43.959 58.42,44.582 58.315,44.582 v2(58.277,44.62)
  Top Layer w0.35: R58.2@44.582,22.682 47.898,22.682 48.136,22.92 v2(48.177,22.92) ; R40.2@47.904,35.48 47.942,35.518 47.942,35.985 v2(48.477,36.52) ; R39.2@58.755,34.188 60.186,34.188 v1(60.186,34.773)
  Top Layer w0.5: Y1.4@53.447,53.403 53.547,53.403 53.897,53.753 53.897,54.34 54.268,54.712 v2(56.274,54.712) ; R43.2@57.218,36.182 58.192,36.182 v2(58.204,36.195)
  POWER w0.35: 52.677,34.925 52.743,34.992 v2(52.743,36.398) ; v1(58.103,39.548) 61.595,39.548 v1(63.119,41.072) ; v2(61.049,57.353) 61.049,58.492 61.127,58.57
  POWER w0.5: J6.1@30.342,60.706 32.128,58.92 54.027,58.92 v2(55.627,57.32) 56.274,56.673 v2(56.274,54.712) ; 56.549,54.82 57.9,53.469 v2(57.9,52.872) ; v1(57.366,39.548) 57.366,43.709 v2(58.277,44.62) ; v2(58.204,36.195) 58.204,34.997 58.277,34.925 ; 66.377,50.07 67.494,50.07 v2(68.034,49.53) ; 66.377,52.019 66.402,52.045 v2(67.374,52.045) ; 66.377,53.188 66.423,53.142 67.764,53.142 v2(67.777,53.129) ; 66.377,54.559 66.591,54.345 v2(68.104,54.345)
  POWER w1.2: v1(47.011,41.638) 47.011,38.016 48.222,36.805 ; 48.477,36.805 50.026,36.805 51.905,34.925 52.677,34.925 55.182,34.925 ; 51.281,50.639 55.353,54.712 v2(56.274,54.712) ; 56.549,54.82 60.299,58.57 61.127,58.57 ; v1(57.366,39.548) v1(58.103,39.548) 58.103,37.846 55.182,34.925 ; v1@60.033,34.925 58.277,34.925 55.182,34.925 ; 61.104,58.547 65.272,58.547 66.377,57.442 66.377,54.559 66.377,53.188 ; v2(62.218,47.498) 63.54,48.82 65.127,48.82 ; 66.423,53.142 66.377,53.096 66.377,52.019 66.377,50.07 65.127,48.82 ; v2(66.434,48.336) 65.95,48.82 65.127,48.82
  Bottom Layer w0.2: C20.1@47.285,43.942 C20.1@47.607,43.621 ; v2(57.9,52.872) 57.922,52.894 58.893,52.894 C4.2@58.916,52.916 ; C5.2@61.024,56.482 61.036,56.494 61.036,57.34 v2(61.049,57.353) ; 62.083,47.714 C12.2@62.083,48.362 ; C11.2@65.435,48.336 v2(66.434,48.336) ; C10.2@67.433,47.32 C9.2@67.433,48.235 67.583,48.385 67.583,48.545 68.034,48.997 v2(68.034,49.53)
  Bottom Layer w0.3: C3.2@55.656,54.686 55.669,54.699 56.261,54.699 v2(56.274,54.712) ; R48.2@57.747,40.8 57.765,40.818 60.68,40.818 60.712,40.786 60.712,39.867 R12.2@60.727,39.853 ; v2(58.277,44.62) 58.315,44.582 58.415,44.582 C52.2@59.077,43.92
  Bottom Layer w0.35: v2(48.177,22.92) 48.177,26.42 49.611,27.854 R50.2@49.611,28.448 49.611,29.586 47.777,31.42 47.777,35.82 v2(48.477,36.52) 48.505,36.549 48.505,36.881 49.025,37.4 Y3.4@49.075,37.4 Y3.1@49.075,38.85 ; C51.2@52.577,35.62 52.652,35.695 52.652,36.266 52.743,36.358 v2(52.743,36.398) ; R45.2@58.075,37.622 58.075,37.62 R45.2@58.077,37.62 C50.2@59.077,37.62 ; R41.2@63.115,35.839 63.115,39.319 R42.2@63.115,40.259 63.117,40.261 63.117,41.069 v1(63.119,41.072) 63.119,43.319 63.13,43.33 63.13,44.744 R31.1@63.14,44.755
  Bottom Layer w0.5: R46.2@56.088,37.592 56.088,37.084 R49.2@55.656,36.652 57.409,36.652 58.077,37.32 R45.2@58.077,37.62 ; R45.2@58.075,37.622 58.075,39.52 v1(58.103,39.548) ; C8.2@67.086,54.127 67.764,53.45 67.764,53.142 v2(67.777,53.129) ; C7.2@67.145,55.405 C6.2@68.11,55.405 68.104,55.399 v2(68.104,54.345)
  Bottom Layer w0.6: v1(60.186,34.773) v1(60.922,34.773) v1(61.684,34.773) 61.724,34.773 62.577,33.92 62.577,29.72 61.584,28.727 R6.1@60.632,28.727
  Bottom Layer w0.8: 47.477,44.92 47.577,44.82 L5.1@49.177,44.82
  other v1: 44.761,41.638 45.511,41.638 46.261,41.638 44.761,42.388 45.511,42.388 46.261,42.388 47.011,42.388 47.761,42.388 50.483,46.533 51.067,46.533 51.626,46.533 49.899,46.558 49.899,47.066 50.483,47.066 51.067,47.066 51.627,47.07 66.434,47.549 39.967,58.801
3V3A: C14.2 C15.2 C16.2 C17.2 J4.7 L2.2 U4.3 U4.6 U4.8 U4.31 U4.34 | length 36.6
  Top Layer w0.25: U4.34@58.724,48.997 58.449,48.997 58.09,48.638 57.897,48.638 v2(57.849,48.59) 57.396,49.043 57.396,49.856 57.737,50.197 U4.31@58.724,50.197 ; v2(62.294,57.353) 63.024,56.623 U4.8@63.024,56.097 ; v2(63.818,57.328) 63.824,57.322 U4.6@63.824,56.097 ; v2(65.013,57.328) 65.024,57.317 U4.3@65.024,56.097
  GND w0.5: J4.7@55.811,60.706 57.197,59.32 60.327,59.32 v2(62.294,57.353)
  POWER w0.25: 57.036,49.936 58.992,51.892 58.992,55.016 60.363,56.388 62.23,56.388
  POWER w0.5: v1(53.83,48.664) 54.54,48.664 v1(54.54,48.676) 54.54,48.692 v1(55.207,48.692) 55.403,48.496 57.755,48.496 v2(57.849,48.59) ; 62.23,56.388 62.294,56.451 v2(62.294,57.353) ; v2(63.818,57.328) 63.818,56.379 63.877,56.32 ; 64.877,56.57 65.013,56.706 v2(65.013,57.328)
  Bottom Layer w0.25: v2(57.849,48.59) 57.916,48.59 58.12,48.387 C14.2@59.101,48.387 ; C17.2@62.243,56.482 62.268,56.507 62.268,57.328 v2(62.294,57.353) ; v2(63.818,57.328) 63.83,57.315 63.83,56.494 C16.2@63.843,56.482 ; v2(65.013,57.328) 65.025,57.316 65.025,56.494 C15.2@65.037,56.482
  Bottom Layer w0.5: v1@55.174,48.725 v1(55.207,48.692)
AVDD_ETH: C46.2 C47.2 C48.2 C49.2 L5.2 U2.9 U2.15 | length 9.6
  Top Layer w0.2: U2.15@52.65,40.739 U2.15@52.652,40.736 ; U2.9@52.651,43.737 U2.9@52.652,43.736
  Top Layer w0.3: v2(51.575,43.739) 51.578,43.736 U2.9@52.652,43.736 ; v2(51.727,40.742) 51.733,40.736 U2.15@52.652,40.736
  Bottom Layer w0.5: C46.2@50.677,40.32 50.678,40.321 C49.2@50.678,41.072 ; C47.2@50.677,45.72 50.677,44.92 L5.2@50.777,44.82 50.678,44.721 C48.2@50.678,43.79 ; v2(51.575,43.739) 51.524,43.79 C48.2@50.678,43.79 ; v2(51.727,40.742) 51.397,41.072 C49.2@50.678,41.072 ; C49.2@50.678,41.072 C48.2@50.678,43.79
CH_GND: C23.1 C24.1 C57.2 H1.1 H2.1 H4.1 J1.S1 J1.S2 J1.S3 J1.S4 J2.3 J3.3 J3.4 J3.5 J3.6 J4.1 P2.R7 P2.S1 P2.S2 | length 157.5
  Top Layer w0.8: J1.S2@44.754,56.536 J1.S4@44.754,60.706 J1.S3@53.404,60.706 ; J1.S1@53.404,56.536 J1.S3@53.404,60.706 ; H1.1@72.877,59.32 70.052,62.145 53.952,62.145 53.423,61.616 53.423,60.725 J1.S3@53.404,60.706
  Top Layer w1.5: J2.3@71.209,46.38 71.235,46.406 73.851,46.406
  GND w0.5: 37.342,30.52 43.146,30.52 P2.R7@43.182,30.556
  GND w0.8: J1.S2@44.754,56.536 J1.S4@44.754,60.706 J1.S3@53.404,60.706 ; J1.S1@53.404,56.536 J1.S3@53.404,60.706 ; J3.6@65.794,32.968 J3.4@65.794,29.618 J3.3@73.414,29.618 ; H1.1@72.877,59.32 72.519,59.32 69.711,62.128 54.453,62.128 53.404,61.079 J1.S3@53.404,60.706
  GND w1.5: P2.S2@37.342,24.686 37.342,30.52 P2.S1@37.342,40.236
  GND w2: H4.1@31.877,45.32 32.123,45.32 37.207,40.236 P2.S1@37.342,40.236
  Bottom Layer w0.8: J1.S4@44.754,60.706 J1.S3@53.404,60.706 53.404,61.079 54.47,62.145 70.052,62.145 H1.1@72.877,59.32
  Bottom Layer w2: H4.1@31.877,45.32 32.258,45.32 P2.S1@37.342,40.236
DVDD: C45.2 U1.23 U1.24 | length 3.8
  Top Layer w0.2: U1.23@55.377,31.444 U1.24@55.377,31.944
  Top Layer w0.25: U1.24@55.377,31.944 56.532,31.944 56.779,32.191 v2(56.846,32.191)
  Bottom Layer w0.25: v2(56.846,32.191) 57.543,31.495 58.251,31.495 C45.2@58.277,31.52
E_MACIF_SEL0: R48.1 U2.28 | length 2
  Top Layer w0.2: U2.28@57.457,41.736 57.459,41.734 58.583,41.734 v2(58.585,41.732)
  Bottom Layer w0.2: R48.1@57.747,41.8 57.781,41.766 58.551,41.766 v2(58.585,41.732)
E_MACIF_SEL1: R47.1 U1.37 U2.29 | length 17.7
  Top Layer w0.2: U1.37@51.752,35.57 51.76,35.578 51.76,36.253 52.693,37.186 59.196,37.186 60.698,38.687 60.698,40.763 v2(59.728,41.732) 59.728,41.813 59.256,42.286 57.507,42.286 U2.29@57.457,42.236
  Bottom Layer w0.2: v2(59.728,41.732) 59.81,41.732 59.913,41.836 R47.1@60.698,41.836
